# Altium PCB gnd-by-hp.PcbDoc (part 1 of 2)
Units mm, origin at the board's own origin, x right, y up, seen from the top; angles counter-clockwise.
Board outline 80 x 100 mm, 4 copper layers (Top Layer, Mid-Layer 1, Internal Plane 1, Bottom Layer); 158 components, 114 nets, 565 pads, 335 vias.
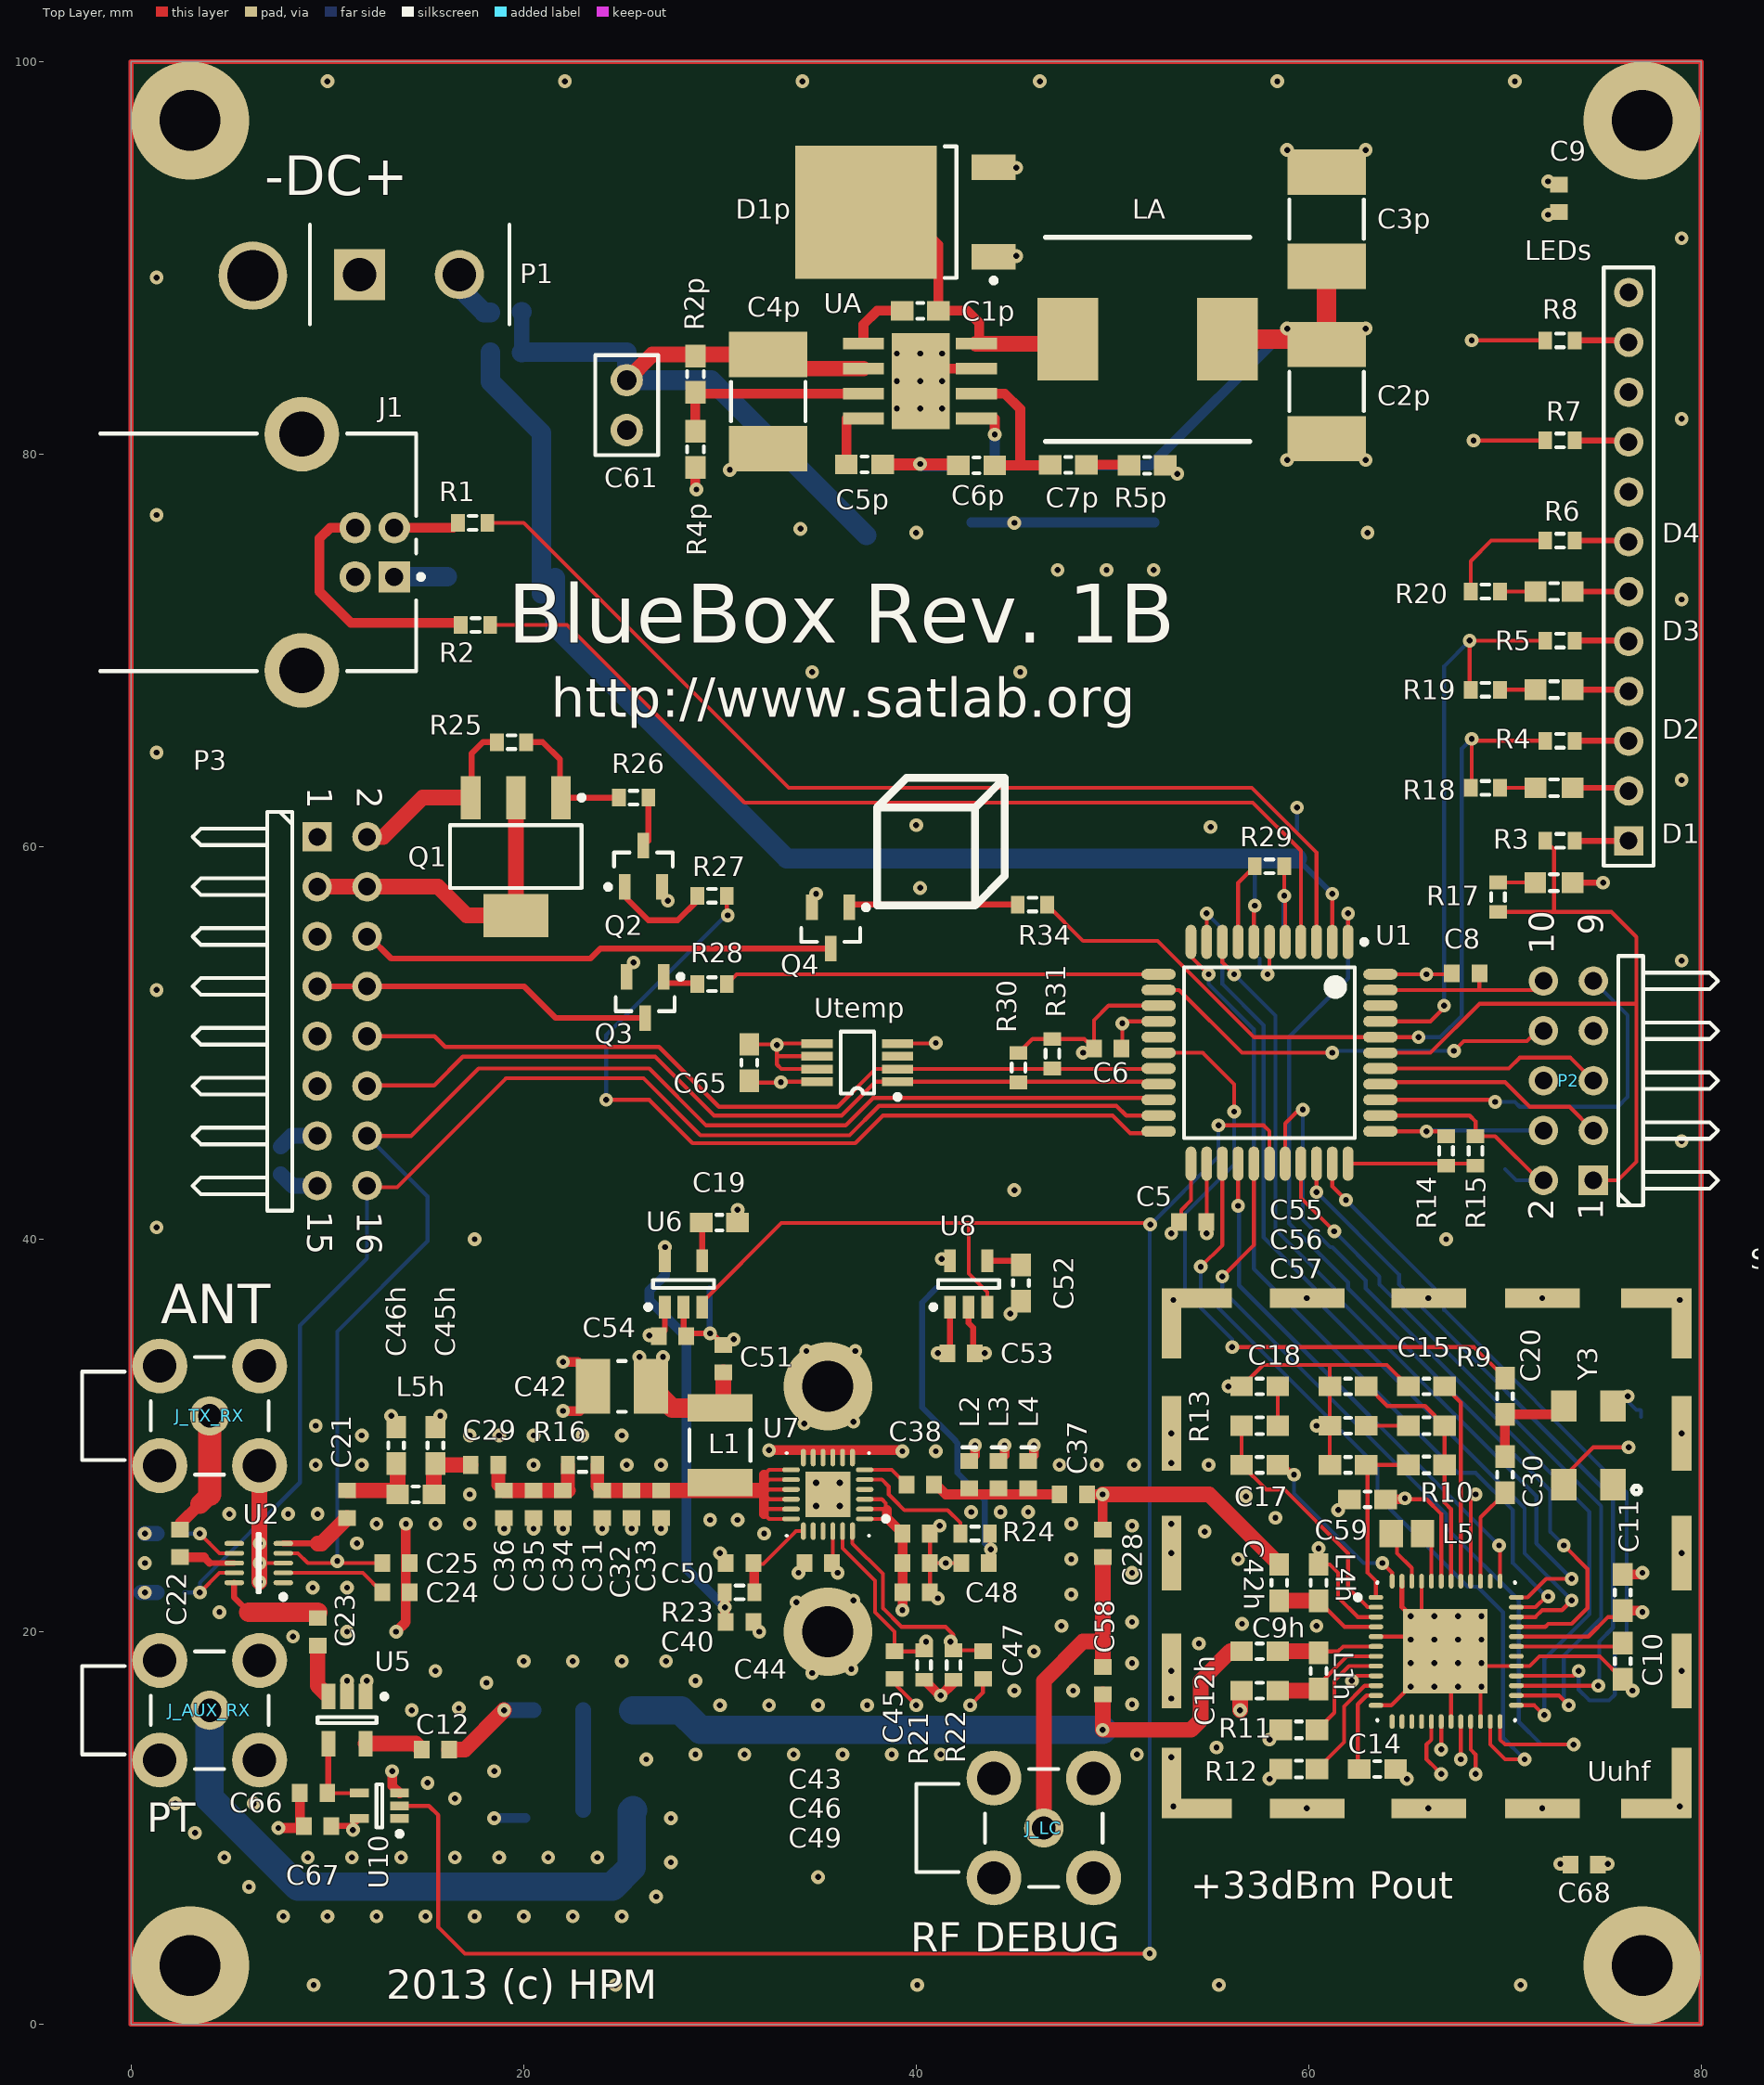
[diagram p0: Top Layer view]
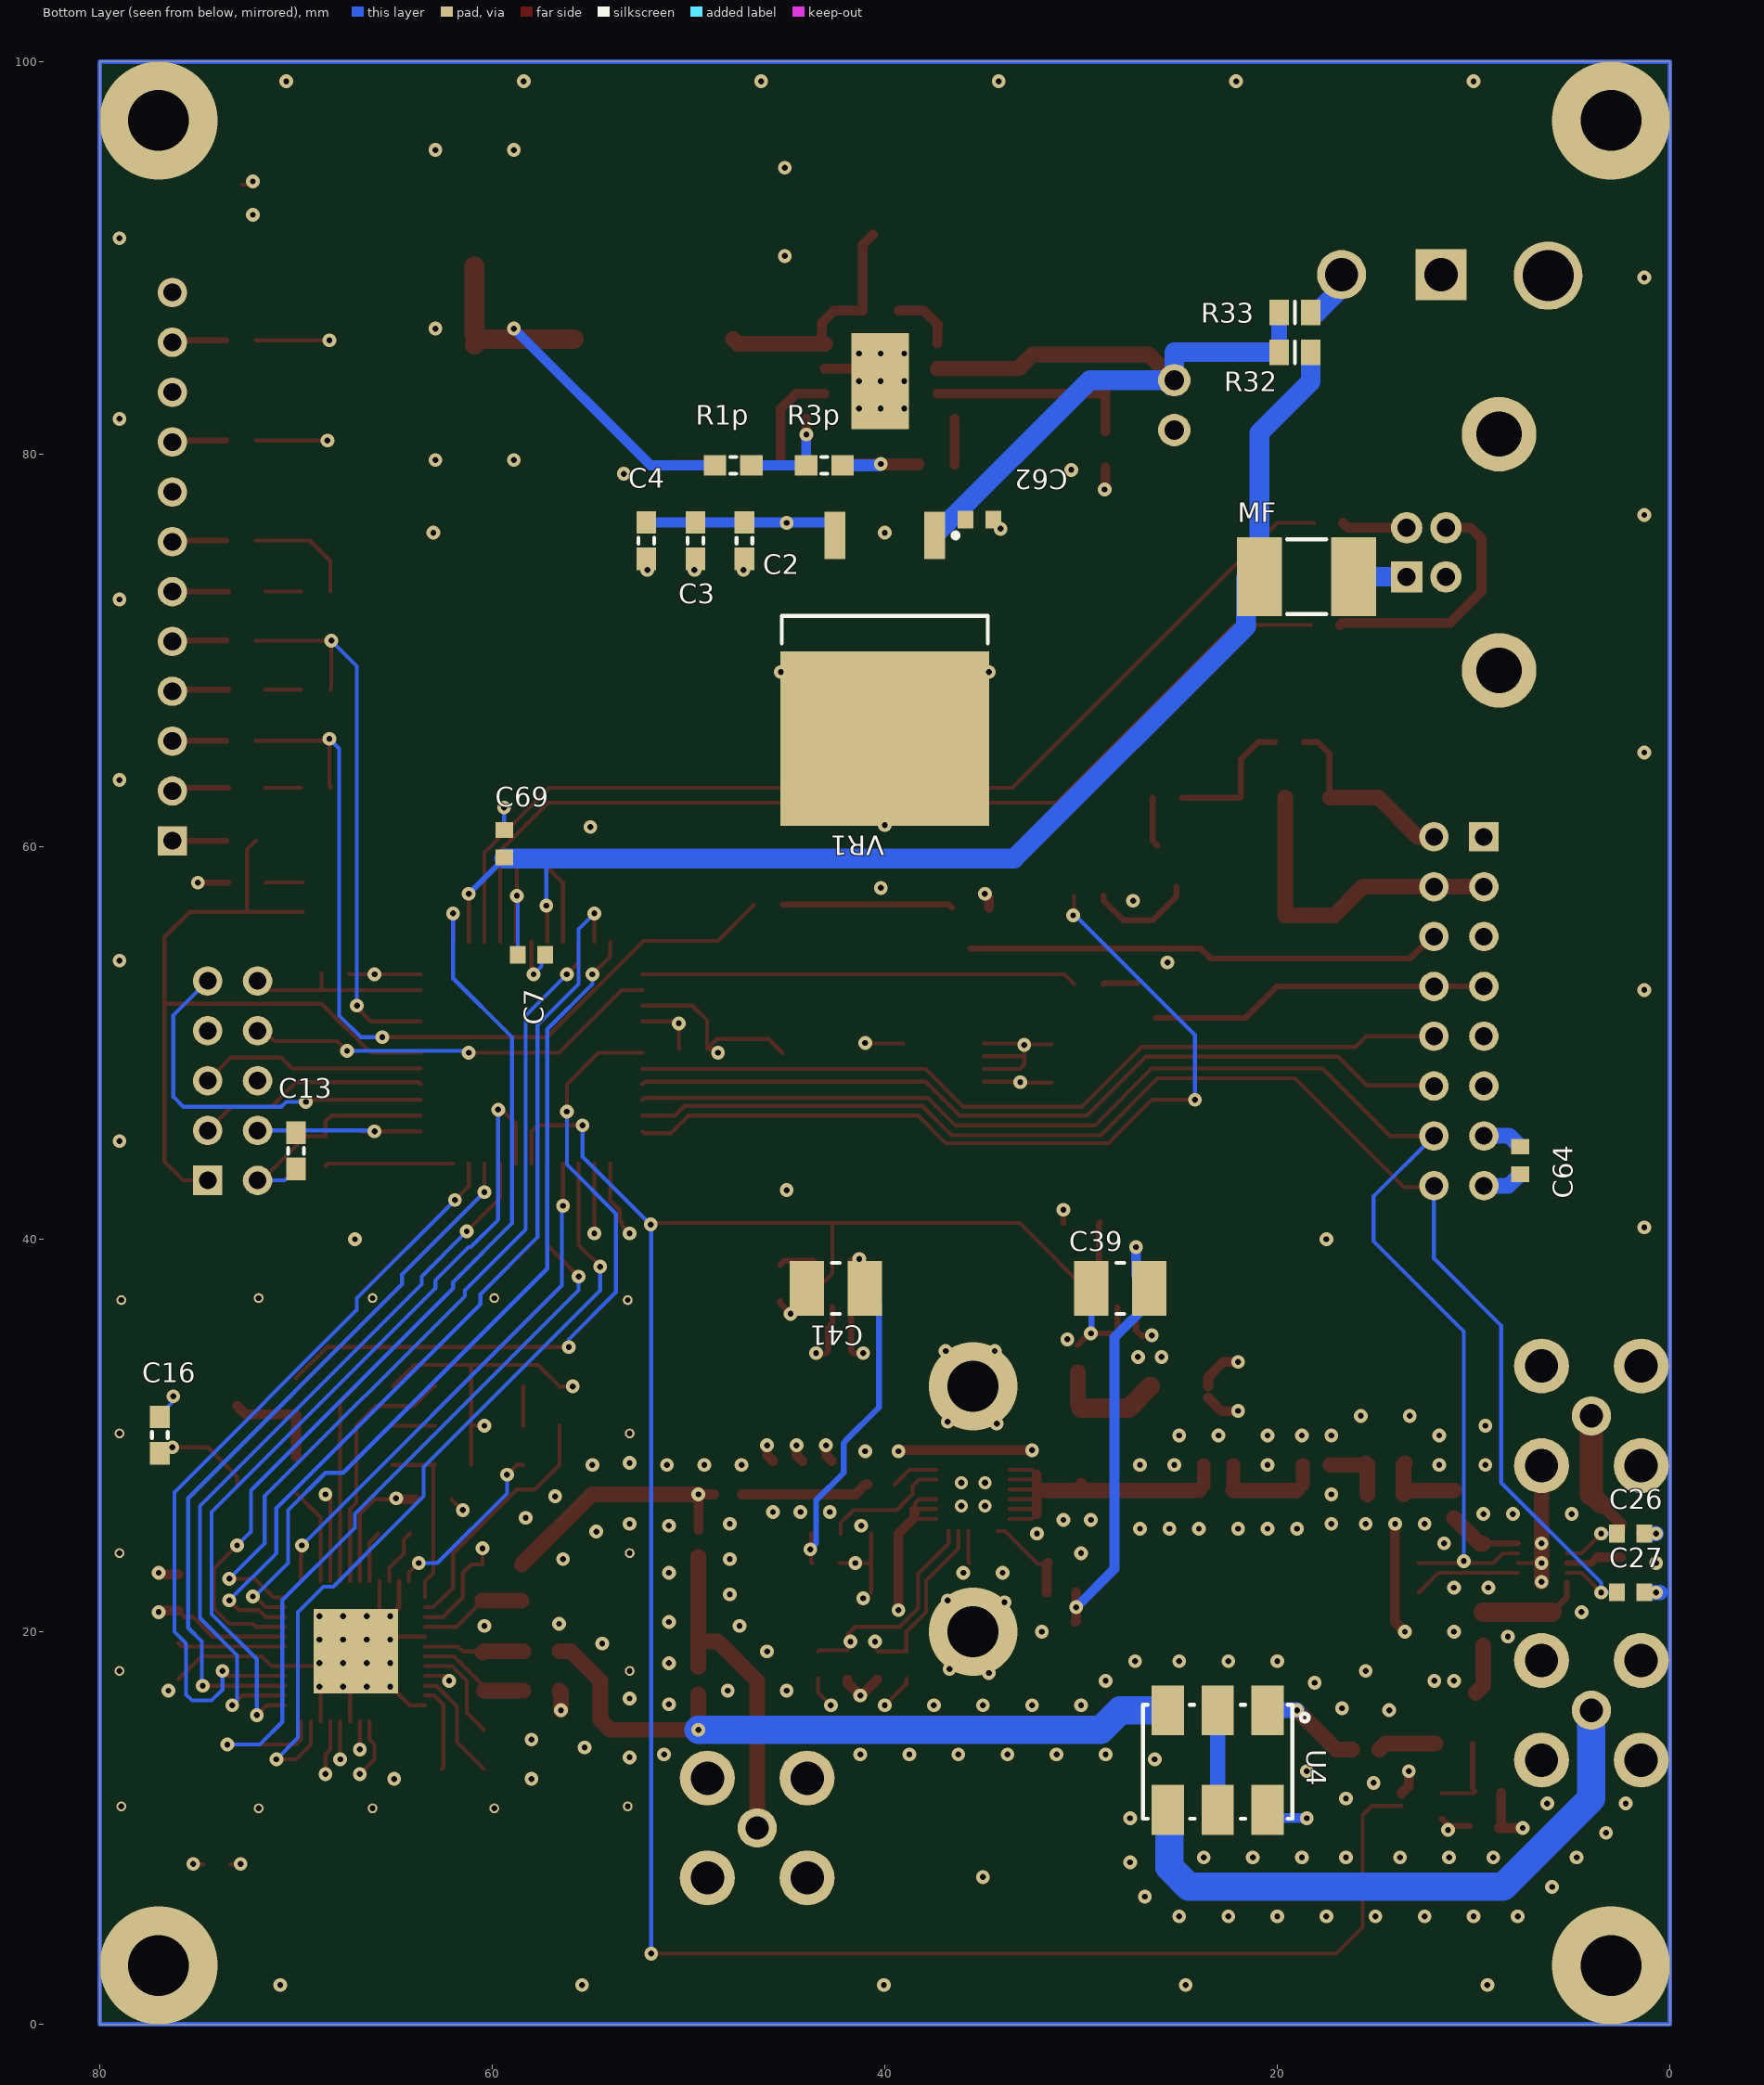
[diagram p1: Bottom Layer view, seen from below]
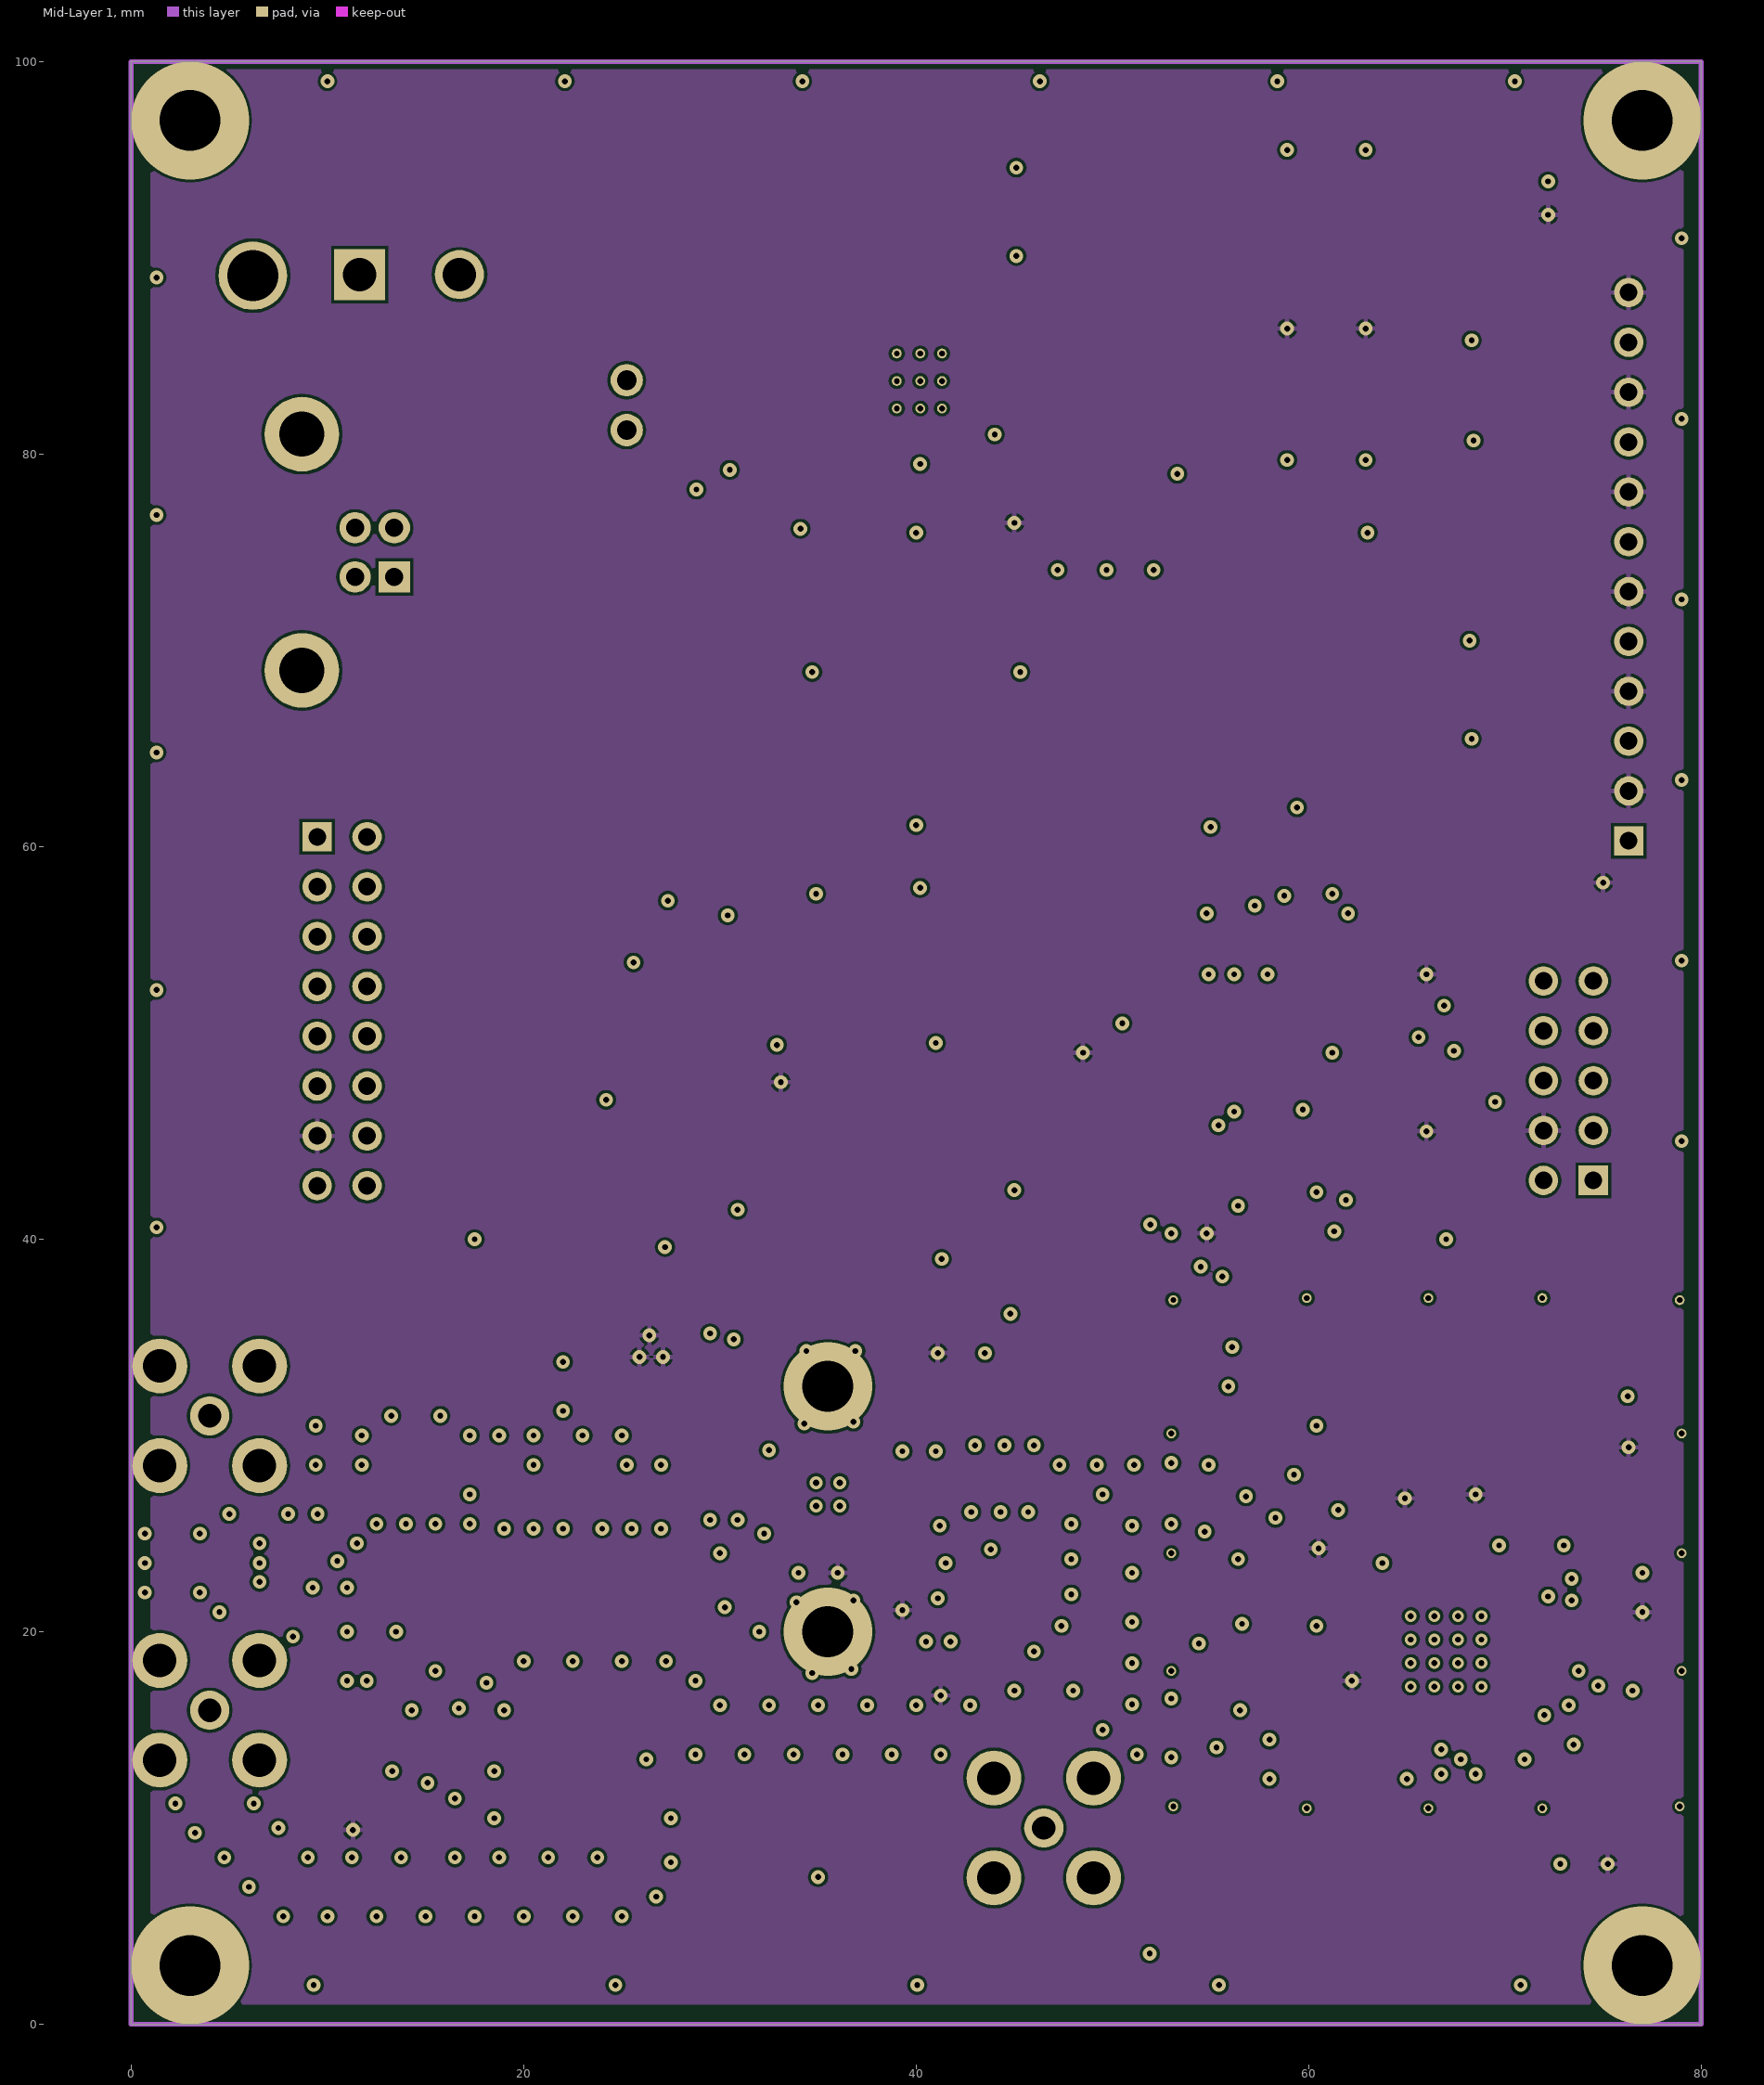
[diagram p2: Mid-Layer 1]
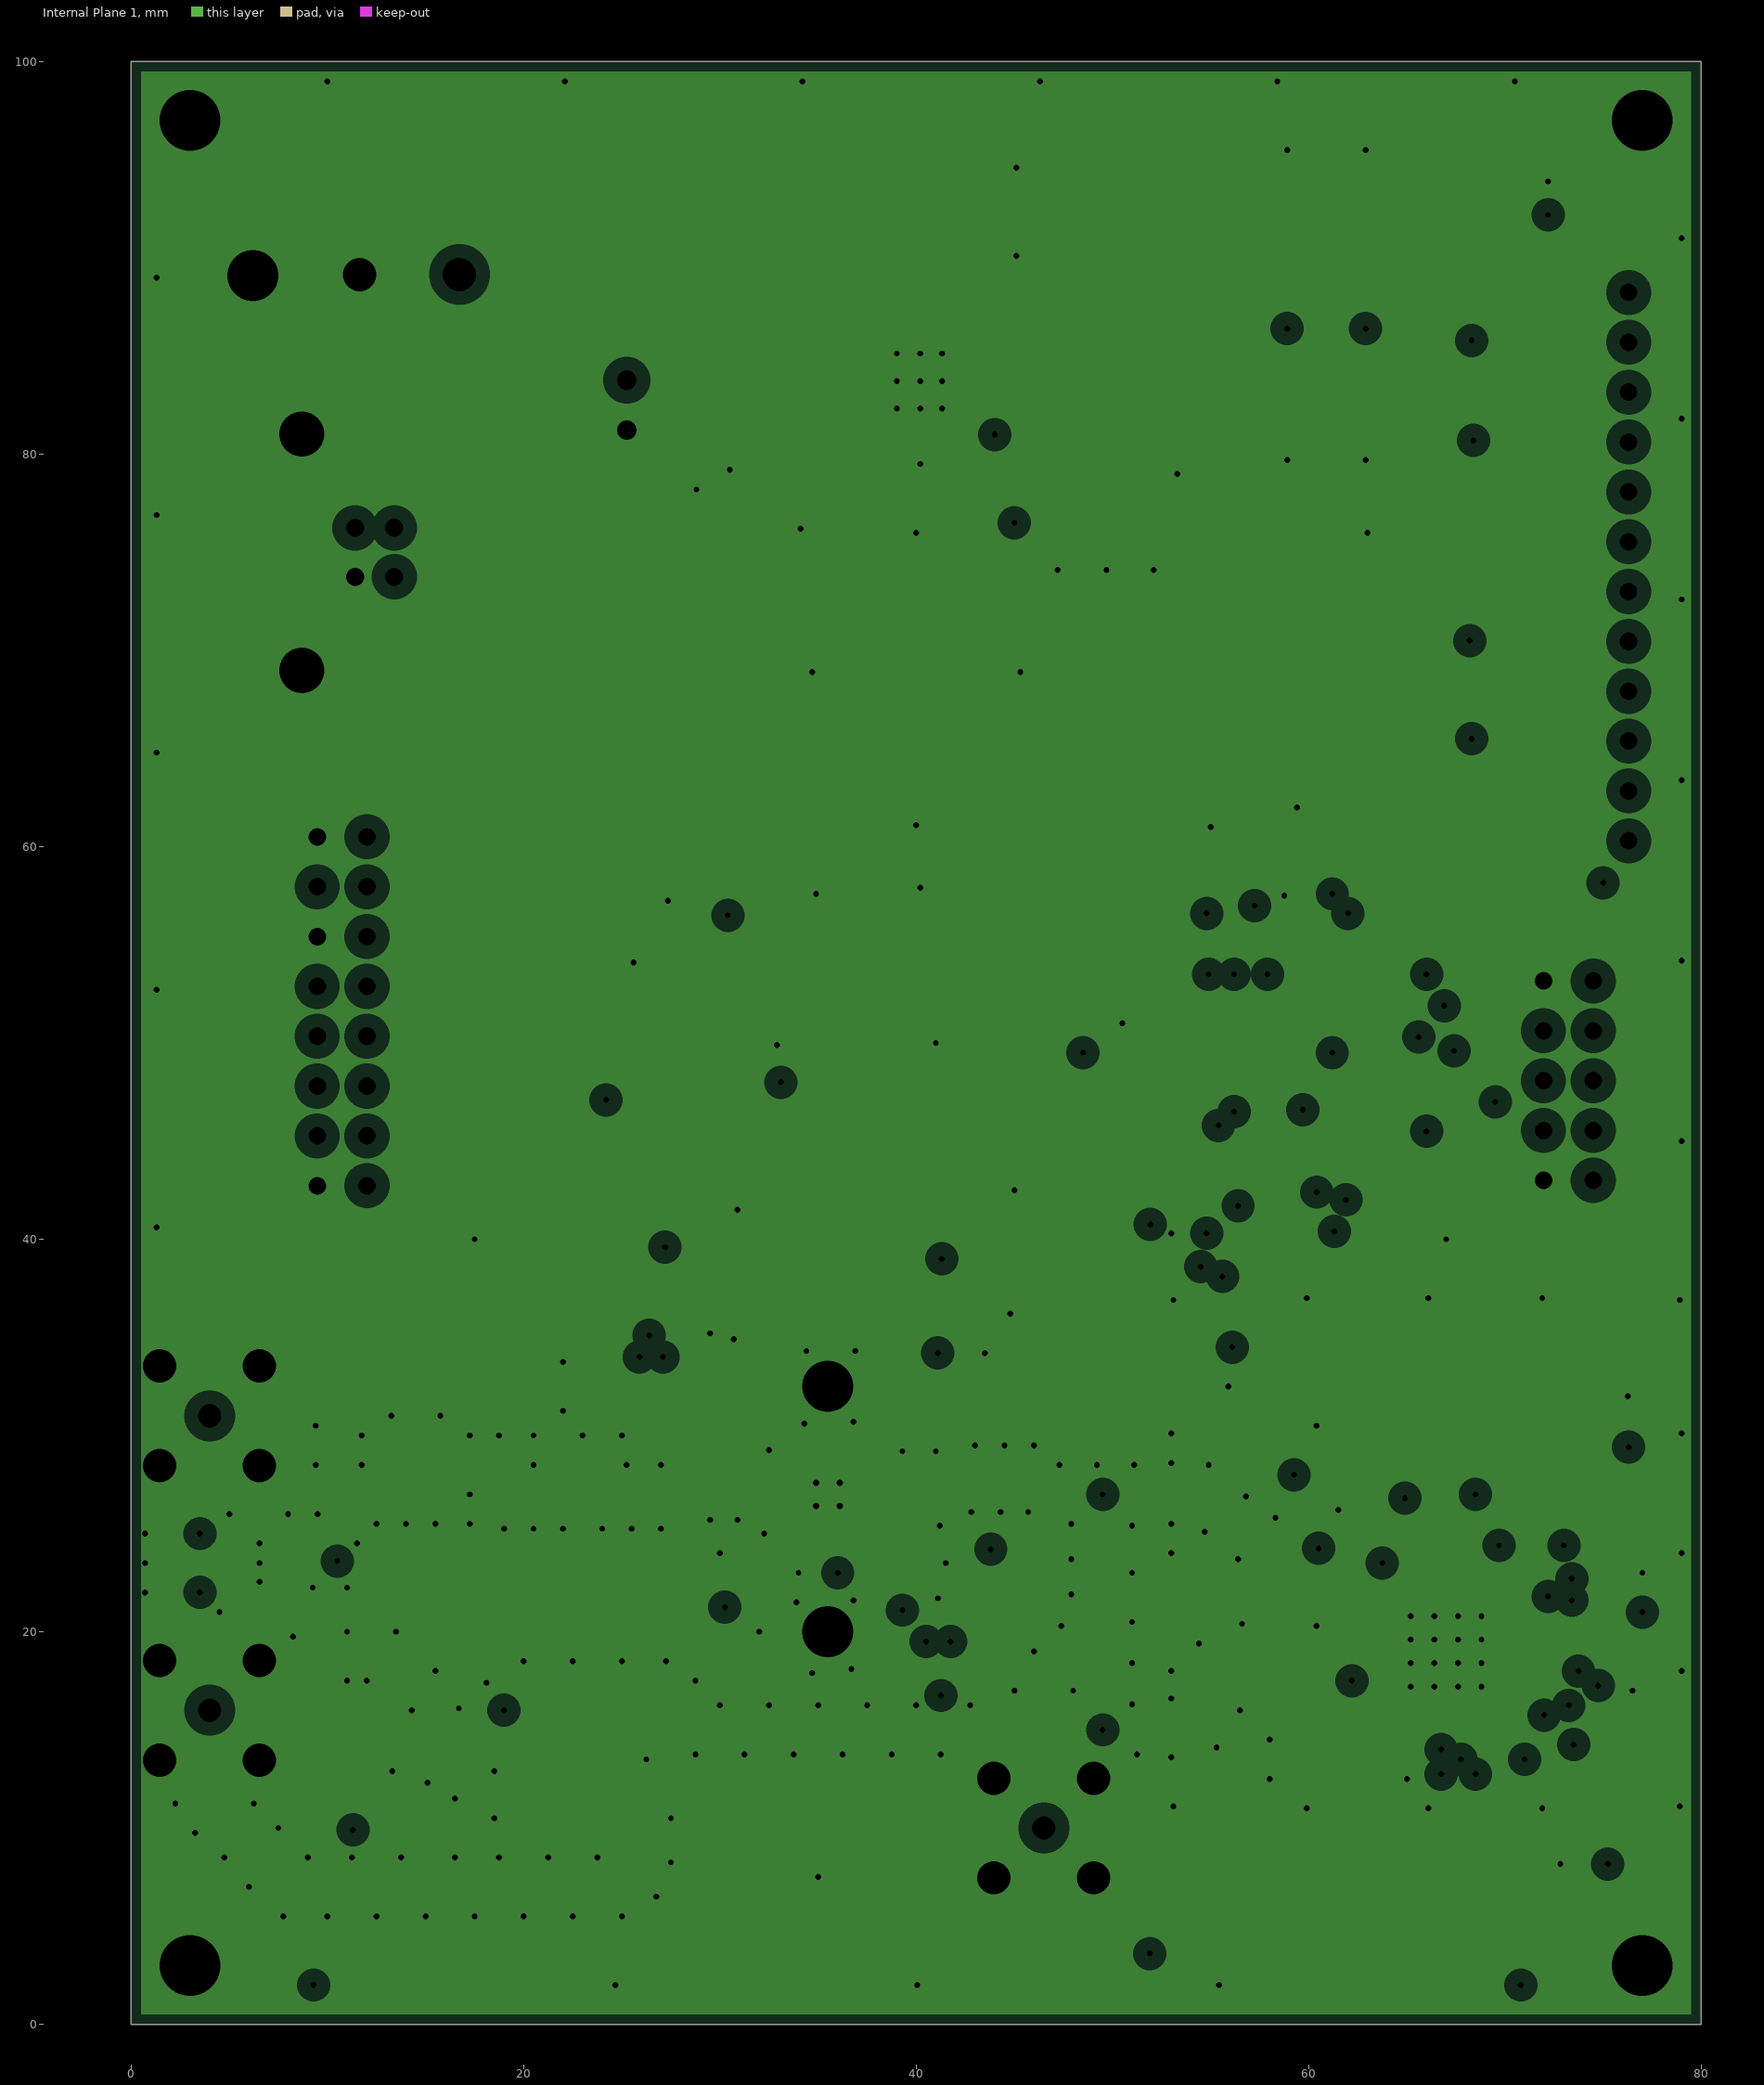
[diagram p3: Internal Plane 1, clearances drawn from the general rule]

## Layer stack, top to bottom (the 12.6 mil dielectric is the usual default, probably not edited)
Top Layer: signal copper 0.0356
Dielectric: core 0.32, FR-4, Dk 4.8
Mid-Layer 1: signal copper 0.0356
Dielectric: prepreg 0.32, FR-4, Dk 4.8
Internal Plane 1: plane copper 0.0356, net GND
Dielectric: core 0.32, FR-4, Dk 4.8
Bottom Layer: signal copper 0.0356

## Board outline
0,0 80,0 80,100 0,100

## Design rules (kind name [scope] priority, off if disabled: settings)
Clearance Clearance_1 [InNamedPolygon('a-gnd') Or  InNamedPolygon('a-gnd')] p1: gap=0.22
Clearance [All] p2: gap=0.15
HoleSize [All] p1: absolutevalues=TRUE maxlimit=4 minlimit=0.3 maxpercent=80.000 minpercent=20.000
HoleToHoleClearance [All] p1: gap=0.1 allowstackedmicrovias=TRUE
MinimumSolderMaskSliver [All] p1: minsoldermaskwidth=0.1
PlaneClearance [All] p1: clearance=0.7
PlaneConnect [All] p1: planeconnectstyle=Direct reliefexpansion=0.3 reliefentries=4 reliefconductorwidth=0.3 reliefairgap=0.2
PolygonConnect PolygonConnect_1 [(InNet('GND') AND IsTrack) OR (InNet('GND') AND IsVia) OR (InNet('GND') AND Uuhf) vs IsNamedPolygon('a-gnd') Or  IsNamedPolygon('a-gnd')] p1: connectstyle=Direct reliefconductorwidth=0.254 reliefentries=4 polygonreliefangle="90 Angle"
PolygonConnect [All] p2: connectstyle=Relief reliefconductorwidth=0.254 reliefentries=4 polygonreliefangle="90 Angle"
RoutingVias [All] p1: holewidth=0.3 width=0.7 viastyle="Through Hole" minholewidth=0.3 minwidth=0.7 maxholewidth=2 maxwidth=1.27
SilkToSilkClearance [All] p1: silktosilkclearance=0.1
SilkscreenOverComponentPads [All] p1: minsilkscreentomaskgap=0.1
SolderMaskExpansion [All] p1: expansion=0.102
Width [All] p1: maxlimit=4 minlimit=0.2 preferedwidth=0.2
21 further rules are at their usual default settings.

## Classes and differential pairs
net class pa_Nets: GND Net*_4 Net*_7 Net*_8 Net*_9 Net*_10 Net*_11 Net*_12 Net*_20 Net*_21 NetC19_2 NetC29_1 NetC37_1 NetC38_1 NetC45_1 NetC47_2 NetC50_2 NetC52_2 NetR24_1 NetU6_3 NetU6_4 NetU8_3 PA_BIAS_EN PA_IN PA_OUT RFOUT VCC VREG1 VREG2
component class gnd-by-hp: C1 C2 C5 C6 C7 C8 C9 C60 C61 C62 C63 C64 C65 C67 C68 C69 C? D1 D2 D3 D4 H1 H2 H3 H4 H5 H6 J1 J2 J4 LEDs MF P1 P2 P3 Q1 Q2 Q3 Q4 R1 R2 R3 R4 R5 R6 R7 R8 R14 R15 R17 R18 R19 R20 R25 R26 R27 R28 R29 R30 R31 R32 R33 R34 U1 U10 Utemp VR1 Y1
component class radio: C3 C4 C9h C10 C11 C12 C12h C13 C14 C15 C16 C17 C18 C20 C21 C22 C23 C24 C25 C26 C27 C28 C30 C42h C45h C46h C55 C56 C57 C58 C59 C66 J_AUX_RX J_LC J_P J_TX_RX L1h L4h L5 L5h R9 R10 R11 R12 R13 S1 S2 SMA1 U2 U3 U4 U5 Uuhf Y3
component class pa: C19 C29 C31 C32 C33 C34 C35 C36 C37 C38 C39 C40 C41 C42 C43 C44 C45 C46 C47 C48 C49 C50 C51 C52 C53 C54 J_D1 L1 L2 L3 L4 R16 R21 R22 R23 R24 U6 U7 U8
net class gnd-by-hp_Nets: 12V CE CLK_OUT D+ D- DATA_CLK DATA_IO EXT_BEKO_PTT EXT_BEKO_PTT_C EXT_LNA_CONTROL EXT_LNA_CONTROL_C GND LED_P LED_R LED_T LED_U1 LED_U2 LED_U3 LNA_V MUXOUT NetC7_1 NetD1_2 NetD2_2 NetD3_2 NetD4_2 NetJ1_1 NetLEDs_1 NetLEDs_3 NetLEDs_5 NetLEDs_7 NetLEDs_9 NetLEDs_11 NetP2_6 NetP2_7 NetP3_9 NetP3_10 NetP3_11 NetP3_12 NetP3_13 NetP3_15 NetP3_17 NetP3_19 NetQ1_1 NetQ2_1 NetQ2_3 NetQ3_1 NetQ4_1 NetR1_2 NetR2_2 NetR29_2 NetU1_9 NetU1_10 NetU1_11 NetU1_12 NetU1_16 NetU1_22 NetU1_26 NetU1_28 NetU1_40 NetU1_41 NetU1_42 NetUSB_4 NetUtemp_3 NetUtemp_5 NetUtemp_6 NetUtemp_7 PA_BIAS_EN PE2 PTT_TX_STAGE_1 RESET RF_RX_C RF_TX_C SCCLK SCL SDA SDATA SLE SREAD SWD TDI_MOSI TEST_A TMS_RST V_BUS VCC VCC_AUX VCC_POWER_DC X1
net class radio_Nets: CE CLK_OUT CPOUT CREG3 DATA_CLK DATA_IO GND L1 L2 LNA_V MUXOUT MUXOUT2 NetC9h_2 NetC10_2 NetC12_2 NetC12h_2 NetC14_2 NetC17_1 NetC17_2 NetC18_1 NetC20_1 NetC21_1 NetC21_2 NetC22_1 NetC23_1 NetC24_1 NetC26_1 NetC28_1 NetC28_2 NetC30_2 NetC42h_1 NetC56_2 NetR11_1 NetR12_2 NetU2_1 NetU3_1 NetU3_2 NetU3_3 NetU3_4 NetU3_5 NetU4_2 NetU5_4 NetU10_1 NetUuhf_13 NetUuhf_14 NetUuhf_15 NetUuhf_16 NetUuhf_17 NetUuhf_18 NetUuhf_20 NetUuhf_21 NetUuhf_30 NetUuhf_38 NetY3_1 PA_IN PA_OUT RF_LC RF_RX RF_RX_AUX RF_RX_C RF_RX_LNA RF_RX_MOD RF_RX_TX RF_TX_C SCCLK SDATA SLE SREAD SWD TEST_A VCC VCOIN X1
net class Supply: PHA VCC
component class power: C1p C2p C3p C4p C5p C6p C7p D1p LA R1p R2p R3p R4p R5p UA

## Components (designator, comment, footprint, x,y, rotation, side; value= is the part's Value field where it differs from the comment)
C1p "Capacitor" C06 40.206,87.306 r0 top
C2 "Capacitor" C06 47.15,75.6 r90 bottom
C2p "CapacitorBig" Cap1812-large 60.907,83.192 r90 top
C3 "Cap Semi" C06 49.65,75.6 r90 bottom
C3p "CapacitorBig" Cap1812-large 60.909,91.973 r270 top
C4 "Cap Semi" C06 52.15,75.6 r90 bottom
C4p "CapacitorBig" Cap1812-large 32.459,82.684 r90 top
C5 "Cap Semi" CAPC1608L 54.077,40.869 r0 top
C5p "Capacitor" C06 37.363,79.477 r180 top
C6 "Cap Semi" CAPC1608L 49.759,49.708 r180 top
C6p "Capacitor" C06 43.076,79.432 r180 top
C7 "Cap Semi" CAPC1608L 58,54.5 r0 bottom
C7p "Capacitor" C06 47.75,79.458 r0 top
C8 "Cap Semi" CAPC1608L 67.996,53.543 r0 top
C9 "Cap Semi" CAPC1608L 72.746,93.04 r270 top
C9h "Cap Semi" C06 57.5,19 r0 top
C10 "Cap Semi" C06 76,18.5 r90 top
C11 "Cap Semi" C06 76,22 r270 top
C12 "Cap Semi" CAPC1608L 15.5,14 r180 top
C12h "Cap Semi" C06 57.5,17 r0 top
C13 "Cap Semi" C06 70,44.5 r90 bottom
C14 "Cap Semi" C06 63.5,13 r180 top
C15 "Cap Semi" C06 66,32.5 r0 top
C16 "Cap Semi" C06 76.937,30.023 r270 bottom
C17 "Cap Semi" C06 57.5,28.5 r0 top
C18 "Cap Semi" C06 57.5,32.5 r180 top
C19 "Capacitor" C06 29.972,40.843 r180 top
C20 "Cap Semi" C06 70,32 r90 top
C21 "Cap Semi" CAPC1608L 11,26.5 r270 top
C22 "Cap Semi" CAPC1608L 2.5,24.5 r90 top
C23 "Cap Semi" CAPC1608L 9.5,20 r90 top
C24 "Cap Semi" CAPC1608L 13.5,22 r0 top
C25 "Cap Semi" CAPC1608L 13.5,23.5 r0 top
C26 "Cap Semi" CAPC1608L 2,25 r180 bottom
C27 "Cap Semi" CAPC1608L 2,22 r180 bottom
C28 "Cap Semi" CAPC1608L 49.5,24.5 r270 top
C29 "Cap Semi" CAPC1608L 18,28.5 r180 top
C30 "Cap Semi" C06 70,28 r270 top
C31 "Cap Semi" CAPC1608L 24,26.5 r90 top
C32 "Cap Semi" CAPC1608L 25.5,26.5 r90 top
C33 "Cap Semi" CAPC1608L 27,26.5 r90 top
C34 "Cap Semi" CAPC1608L 22,26.5 r90 top
C35 "Cap Semi" CAPC1608L 20.5,26.5 r90 top
C36 "Cap Semi" CAPC1608L 19,26.5 r90 top
C37 "Cap Semi" CAPC1608L 48,27 r0 top
C38 "Cap Semi" CAPC1608L 40.2,27.5 r0 top
C39 "CapacitorBig" C1210 28,37.5 r0 bottom
C40 "Cap Semi" CAPC1608L 31,20.5 r180 top
C41 "CapacitorBig" C1210 42.5,37.5 r180 bottom
C42 "CapacitorBig" C1210 25,32.5 r180 top
C42h "Cap Semi" C06 58.5,22.5 r90 top
C43 "Cap Semi" CAPC1608L 40,25 r0 top
C44 "Cap Semi" CAPC1608L 35,23.5 r180 top
C45 "Cap Semi" CAPC1608L 38.9,18.3 r270 top
C45h "Cap Semi" C06 15.5,29.5 r270 top
C46 "Cap Semi" CAPC1608L 40,23.5 r0 top
C46h "Cap Semi" C06 13.5,29.5 r270 top
C47 "Cap Semi" CAPC1608L 43.4,18.3 r90 top
C48 "Cap Semi" CAPC1608L 43,23.5 r180 top
C49 "Cap Semi" CAPC1608L 40,22 r0 top
C50 "Cap Semi" CAPC1608L 31,23.5 r0 top
C51 "Cap Semi" CAPC1608L 30.175,33.909 r270 top
C52 "Capacitor" C06 45.339,37.77 r90 top
C53 "Cap Semi" CAPC1608L 42.291,34.188 r180 top
C54 "Cap Semi" CAPC1608L 27.584,35.052 r180 top
C55 "Cap Semi" C06 62,32.5 r0 top
C56 "Cap Semi" C06 62,30.5 r0 top
C57 "Cap Semi" C06 62,28.5 r0 top
C58 "Cap Semi" CAPC1608L 49.5,17.5 r90 top
C59 "Cap Semi" C06 63,26.746 r0 top
C61 "Cap" CAPR2.54-5.1x3.2 25.25,82.5 r90 top
C62 "Cap Semi" CAPC1608L 35.179,76.657 r0 bottom
C64 "Cap Semi" CAPC1608L 7.626,44.018 r90 bottom
C65 "Capacitor" C06 31.5,49 r270 top
C66 "Cap Semi" CAPC1608L 9.296,11.786 r180 top
C67 "Cap Semi" CAPC1608L 9.505,10.1 r0 top
C68 "Cap Semi" CAPC1608L 74.041,8.141 r0 top
C69 "Cap Semi" CAPC1608L 59.394,60.147 r270 bottom
D1 "LED" L06 72.492,58.166 r180 top
D1p "MBRD360" TO228P1003X238-3N 39.446,92.329 r180 top
D2 "LED" L06 72.5,63 r180 top
D3 "LED" L06 72.5,68 r180 top
D4 "LED" L06 72.5,73 r180 top
J1 "1-1470156-1" 1-1470156 -1.6,75 r180 top
J_AUX_RX "COAX-F" MCX5.08-H5 4,16 r0 top
J_LC "COAX-F" MCX5.08-H5 46.5,10 r0 top
J_TX_RX "COAX-F" MCX5.08-H5 4,31 r0 top
L1 "Inductor" INDC4532L 30,29.5 r90 top
L1h "Inductor" C06 60.5,18 r90 top
L2 "Inductor" INDC1608L 42.7,28 r270 top
L3 "Inductor" INDC1608L 44.2,28 r270 top
L4 "Inductor" INDC1608L 45.7,28 r270 top
L4h "Inductor" C06 60.5,22.5 r90 top
L5 "Inductor" INDC2012L 65,25 r0 top
L5h "Inductor" C06 14.5,27 r180 top
LA "Inductor" B82464-G4 46.455,91.193 r0 top
LEDs "Header 12" HDR1X12 76.3,60.3 r90 top
MF "Multifuse" Cap1812-large 18.511,73.76 r180 bottom
P1 "Header 2" HDR1X2 19.954,88.163 r0 top
P2 "Header 5X2H" HDR2X5H 74.5,43 r90 top
P3 "Header 8X2H" HDR2X8H 9.48,60.503 r270 top
Q1 "BSP250" SOT223_N 19.6,59.5 r270 top
Q2 "BSH105" SOT23_N 26.1,59 r90 top
Q3 "BSH105" SOT23_N 26.191,52.324 r270 top
Q4 "BSH105" SOT23_N 35.64,55.855 r270 top
R1 "Res Semi" RESC1608L 17.4,76.5 r0 top
R1p "Resistor" R06 47.725,79.432 r0 bottom
R2 "Res Semi" RESC1608L 17.546,71.296 r0 top
R2p "Res Semi" R06 28.751,84.081 r90 top
R3 "Res Semi" RESC1608L 72.8,60.3 r0 top
R3p "Resistor" R06 43.076,79.432 r0 bottom
R4 "Res Semi" RESC1608L 72.8,65.4 r0 top
R4p "Res Semi" R06 28.751,80.245 r90 top
R5 "Res Semi" RESC1608L 72.8,70.5 r0 top
R5p "Resistor" R06 51.763,79.432 r0 top
R6 "Res Semi" RESC1608L 72.8,75.6 r0 top
R7 "Res Semi" RESC1608L 72.8,80.7 r0 top
R8 "Res Semi" RESC1608L 72.8,85.8 r0 top
R9 "Res Semi" R06 66,30.5 r0 top
R10 "Res Semi" R06 66,28.5 r0 top
R11 "Res Semi" R06 59.5,15 r180 top
R12 "Res Semi" R06 59.5,13 r0 top
R13 "Res Semi" R06 57.5,30.5 r0 top
R14 "Res Semi" RESC1608L 67,44.5 r90 top
R15 "Res Semi" RESC1608L 68.5,44.5 r270 top
R16 "Res Semi" RESC1608L 23,28.5 r180 top
R17 "Res Semi" RESC1608L 69.647,57.429 r270 top
R18 "Res Semi" RESC1608L 69,63 r180 top
R19 "Res Semi" RESC1608L 69,68 r180 top
R20 "Res Semi" RESC1608L 69,73 r180 top
R21 "Res Semi" RESC1608L 40.4,18.3 r270 top
R22 "Res Semi" RESC1608L 41.9,18.3 r270 top
R23 "Res Semi" RESC1608L 31,22 r0 top
R24 "Res Semi" RESC1608L 43,25 r0 top
R25 "Res Semi" RESC1608L 19.38,65.329 r180 top
R26 "Res Semi" RESC1608L 25.6,62.5 r0 top
R27 "Res Semi" RESC1608L 29.6,57.5 r0 top
R28 "Res Semi" RESC1608L 29.6,53 r0 top
R29 "Res Semi" RESC1608L 58,59 r180 top
R30 "Res Semi" RESC1608L 45.212,48.743 r90 top
R31 "Res Semi" RESC1608L 46.939,49.454 r90 top
R32 "Res Semi" RESC2012L 19.101,85.192 r0 bottom
R33 "Res Semi" RESC2012L 19.101,87.224 r0 bottom
R34 "Res Semi" RESC1608L 45.923,57.048 r0 top
S2 "rf_shield" rf_can_shield 52.5,37.5 r270 top locked
U1 "ATmega32u4" 44A_N 58,49.5 r270 top
U2 "RX/TX Switch" FLP10 6.5,23.5 r180 top
U4 "ADP-2-1" ADP-2-1 20.5,16 r270 bottom
U5 "RF2314" SOT95P280X144-5M 11,15.5 r270 top
U6 "TC1185" "SOT23 - 5 for microchip" 28.143,37.719 r90 top
U7 "RF6886TR7" QFN24-4-4 35.5,27 r180 top
U8 "TC1185" "SOT23 - 5 for microchip" 42.672,37.719 r90 top
U10 "MC74HC inv" "SOT353 for MC74HC" 12.649,11.125 r180 top
UA "TPS54332DDA" 8SO_PowerPAD 37.311,85.63 r0 top
Utemp "DS75LXU+" uSOP8 37,49 r90 top
Uuhf "ADF7021" QFN50P700X700X100-48M 67,19 r0 top
VR1 "Volt Reg" TO254P1510-3_4N 40.005,69.063 r270 bottom
Y3 "FOX924B" Fox924 73,27.5 r90 top

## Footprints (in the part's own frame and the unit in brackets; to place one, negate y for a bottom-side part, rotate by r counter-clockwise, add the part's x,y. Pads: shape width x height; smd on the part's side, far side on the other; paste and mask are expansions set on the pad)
1-1470156 [mm] "Connector; USB1.1, Type B, Thru-Hole; 4 Position; Right Angle"
  rect 1.6x1.6 hole 0.92: 1(-15.01,1.25)
  round 1.6 hole 0.92: 2(-15.01,-1.25) 3(-13.01,-1.25) 4(-13.01,1.25)
  round 3.8 hole 2.3: 5(-10.3,6.02) 6(-10.3,-6.02)
  silkscreen extent -16.49,-6.05 -0.02,6.05
8SO_PowerPAD [mm] "TPS SO8 PowerPAD (for TPS54332)"
  rect 2.1x0.6 smd: 1(0,0) 2(0,-1.27) 3(0,-2.54) 4(0,-3.81) 5(5.75,-3.81) 6(5.75,-2.54) 7(5.75,-1.27) 8(5.75,0)
  round 0.5 hole 0.3: 9(1.7,-3.3) 9(1.7,-1.9) 9(1.7,-0.5) 9(2.9,-3.3) 9(2.9,-1.9) 9(2.9,-0.5) 9(4,-3.3) 9(4,-1.9) 9(4,-0.5)
  rect 2.94x4.89 smd: 9(2.921,-1.905)
  rect 2.94x4.89 smd far side: 9(2.921,-1.905)
  body extent 0.85,-4.5 4.85,0.58, height 2.5
44A_N [mm] "Thin QFP, 44-Leads, Body 10x10mm, Pitch 0.8mm, IPC Medium Density"
  oval 1.75x0.55 smd: 1(-5.65,4) 2(-5.65,3.2) 3(-5.65,2.4) 4(-5.65,1.6) 5(-5.65,0.8) 6(-5.65,0) 7(-5.65,-0.8) 8(-5.65,-1.6) 9(-5.65,-2.4) 10(-5.65,-3.2) 11(-5.65,-4) 23(5.65,-4) 24(5.65,-3.2) 25(5.65,-2.4) 26(5.65,-1.6) 27(5.65,-0.8) 28(5.65,0) 29(5.65,0.8) 30(5.65,1.6) 31(5.65,2.4) 32(5.65,3.2) 33(5.65,4)
  oval 0.55x1.75 smd: 12(-4,-5.65) 13(-3.2,-5.65) 14(-2.4,-5.65) 15(-1.6,-5.65) 16(-0.8,-5.65) 17(0,-5.65) 18(0.8,-5.65) 19(1.6,-5.65) 20(2.4,-5.65) 21(3.2,-5.65) 22(4,-5.65) 34(4,5.65) 35(3.2,5.65) 36(2.4,5.65) 37(1.6,5.65) 38(0.8,5.65) 39(0,5.65) 40(-0.8,5.65) 41(-1.6,5.65) 42(-2.4,5.65) 43(-3.2,5.65) 44(-4,5.65)
  silkscreen extent -5.77,-4.35 4.35,4.95, body extent -5,-5 5,5, height 1.2
ADP-2-1 [mm]
  rect 2.54x1.65 smd: 1(0,0) 2(0,-2.54) 3(0,-5.08) 4(5.08,-5.08) 5(5.08,-2.54) 6(5.08,0)
  silkscreen extent -0.28,-6.35 5.52,2.1
B82464-G4 [mm] "SMT Power Inductors B82464-G4"
  rect 3.1x4.2 smd: 1(1.27,-5.334) 2(9.398,-5.334)
  silkscreen extent 0.14,-10.54 10.54,-0.14, body extent 0.33,-10.35 10.33,-0.35, height 5
C06 [mm] "Chip Capacitor, 2-Leads, Body 1.6x0.8mm, IPC Low Density"
  rect 1.15x1 smd: 1(-0.925,0) 2(0.925,0)
  silkscreen extent -0.15,-0.4 0.15,0.4, body extent -0.8,-0.41 0.8,0.41, height 0.82
C1210 [mm] "Chip Capacitor, 2-Leads, Body 3.2x2.5mm, IPC Low Density"
  rect 1.75x2.8 smd: 1(-1.475,0) 2(1.475,0)
  silkscreen extent -0.2,-1.3 0.2,1.3, body extent -1.75,-1.35 1.75,1.35, height 2.7
Cap1812-large [mm] "Chip Resistor; Body 1812"
  rect 2.3x4 smd: 1(-2.4,0) 2(2.4,0)
  silkscreen extent -1,-1.9 1,1.9, body extent -2.89,-2 2.9,2, height 2.7
CAPC1608L [mm] "Chip Capacitor, Body 1.6x0.8mm, IPC High Density"
  rect 0.8x0.9 smd: 1(-0.7,0) 2(0.7,0)
  body extent -0.87,-0.48 0.87,0.48, height 1.3
CAPR2.54-5.1x3.2 [mm] "Capacitor, Ceramic, Thru-Hole, Dipped Radial; Body 5.1 x 3.2 mm (WxT) Pin Spacing 2.54 mm (typ)"
  round 1.65 hole 1: 1(-1.27,0) 2(1.27,0)
  silkscreen extent -2.55,-1.6 2.55,1.6
FLP10 [mm] "Used in NJG1519KC1-TE3, a IC MMIC Switch SP4t FLP10"
  oval 1x0.25 smd: 1(-1.25,1) 2(-1.25,0.5) 3(-1.25,0) 4(-1.25,-0.5) 5(-1.25,-1) 6(1.25,-1) 7(1.25,-0.5) 8(1.25,0) 9(1.25,0.5) 10(1.25,1)
  silkscreen extent -1.38,-1.5 0.08,1.85, body extent -1.2,-1.5 1.2,1.5, height 0.8
Fox924 [mm]
  rect 1.6x1.3 smd: 1(0,-2.5) 2(4,-2.5) 3(4,0) 4(0,0)
  silkscreen extent -0.47,-3.9 -0.08,-3.5, body extent -0.53,-2.83 4.5,0.35, height 1.5
HDR1X2 [mm] "Connector; Header; 2 Position"
  rect 2.6x2.6 hole 1.7: 1(-8.306,0.991)
  round 2.5 hole 1.7: 2(-3.226,0.991)
  silkscreen extent -10.85,-1.55 -0.69,3.53
HDR1X12 [mm] "Connector; Header; 12 Position"
  rect 1.5x1.5 hole 0.9: 1(0,0)
  round 1.5 hole 0.9: 2(2.54,0) 3(5.08,0) 4(7.62,0) 5(10.16,0) 6(12.7,0) 7(15.24,0) 8(17.78,0) 9(20.32,0) 10(22.86,0) 11(25.4,0) 12(27.94,0)
  silkscreen extent -1.27,-1.27 29.21,1.27
HDR2X5H [mm] "Connector; Header; 5x2 Position; Right Angle"
  rect 1.5x1.5 hole 0.9: 1(0,0)
  round 1.5 hole 0.9: 2(0,2.54) 3(2.54,0) 4(2.54,2.54) 5(5.08,0) 6(5.08,2.54) 7(7.62,0) 8(7.62,2.54) 9(10.16,0) 10(10.16,2.54)
  silkscreen extent -1.27,-6.35 11.43,-1.27
HDR2X8H [mm] "Connector; Header; 8x2 Position; Right Angle"
  rect 1.5x1.5 hole 0.9: 1(0,0)
  round 1.5 hole 0.9: 2(0,2.54) 3(2.54,0) 4(2.54,2.54) 5(5.08,0) 6(5.08,2.54) 7(7.62,0) 8(7.62,2.54) 9(10.16,0) 10(10.16,2.54) 11(12.7,0) 12(12.7,2.54) 13(15.24,0) 14(15.24,2.54) 15(17.78,0) 16(17.78,2.54)
  silkscreen extent -1.27,-6.35 19.05,-1.27
INDC1608L [mm] "Chip Inductor, Body 1.6x0.8mm, IPC High Density"
  rect 0.8x0.9 smd: 1(-0.7,0) 2(0.7,0)
  silkscreen extent -1.4,-0.35 -1.4,0.35, body extent -0.87,-0.48 0.87,0.48, height 0.55
INDC2012L [mm] "Chip Inductor, Body 2.0x1.2mm, IPC High Density"
  rect 1.2x1.4 smd: 1(-0.8,0) 2(0.8,0)
  body extent -1.1,-0.7 1.1,0.7, height 0.55
INDC4532L [mm] "Chip Inductor, Body 4.5x3.2mm, IPC High Density"
  rect 1.4x3.3 smd: 1(-1.9,0) 2(1.9,0)
  silkscreen extent -0.8,-1.55 0.8,1.55, body extent -2.4,-1.7 2.4,1.7, height 0.55
L06 [mm] "Chip LED, 2-Leads, Body 1.6x0.8mm, IPC Low Density"
  rect 1.1x1.05 smd: 1(-0.95,0) 2(0.95,0)
  silkscreen extent -0.2,-0.43 0.2,0.43, body extent -0.85,-0.45 0.85,0.45, height 0.9
MCX5.08-H5 [mm] "Connector; RF Coaxial, MCX, Thru-Hole; 5 Position; Right-Angle"
  round 2 hole 1.2: 1(0,0)
  round 2.8 hole 1.7: 2(-2.54,-2.54) 3(2.54,-2.54) 4(2.54,2.54) 5(-2.54,2.54)
  silkscreen extent -6.5,-3 3,3
QFN24-4-4 [mm] "QFN, 24-Leads, Body 4,2x4,2mm (max), Pitch 0,50mm, IPC Medium Density"
  oval 0.9x0.25 smd: 1(-1.875,1.25) 2(-1.875,0.75) 3(-1.875,0.25) 4(-1.875,-0.25) 5(-1.875,-0.75) 6(-1.875,-1.25) 13(1.875,-1.25) 14(1.875,-0.75) 15(1.875,-0.25) 16(1.875,0.25) 17(1.875,0.75) 18(1.875,1.25)
  oval 0.25x0.9 smd: 7(-1.25,-1.875) 8(-0.75,-1.875) 9(-0.25,-1.875) 10(0.25,-1.875) 11(0.75,-1.875) 12(1.25,-1.875) 19(1.25,1.875) 20(0.75,1.875) 21(0.25,1.875) 22(-0.25,1.875) 23(-0.75,1.875) 24(-1.25,1.875)
  rect 2.3x2.3 smd: 25(0,0)
  silkscreen extent -3.08,-2.1 2.1,2.1, body extent -2.07,-2.07 2.07,2.07, height 0.85
QFN50P700X700X100-48M [mm] "QFN, 48-Leads, Body 7,0x7,0mm (max), Pitch 0,50mm, IPC Low Density"
  oval 0.75x0.25 smd: 1(-3.575,2.75) 2(-3.575,2.25) 3(-3.575,1.75) 4(-3.575,1.25) 5(-3.575,0.75) 6(-3.575,0.25) 7(-3.575,-0.25) 8(-3.575,-0.75) 9(-3.575,-1.25) 10(-3.575,-1.75) 11(-3.575,-2.25) 12(-3.575,-2.75) 25(3.575,-2.75) 26(3.575,-2.25) 27(3.575,-1.75) 28(3.575,-1.25) 29(3.575,-0.75) 30(3.575,-0.25) 31(3.575,0.25) 32(3.575,0.75) 33(3.575,1.25) 34(3.575,1.75) 35(3.575,2.25) 36(3.575,2.75)
  oval 0.25x0.75 smd: 13(-2.75,-3.575) 14(-2.25,-3.575) 15(-1.75,-3.575) 16(-1.25,-3.575) 17(-0.75,-3.575) 18(-0.25,-3.575) 19(0.25,-3.575) 20(0.75,-3.575) 21(1.25,-3.575) 22(1.75,-3.575) 23(2.25,-3.575) 24(2.75,-3.575) 37(2.75,3.575) 38(2.25,3.575) 39(1.75,3.575) 40(1.25,3.575) 41(0.75,3.575) 42(0.25,3.575) 43(-0.25,3.575) 44(-0.75,3.575) 45(-1.25,3.575) 46(-1.75,3.575) 47(-2.25,3.575) 48(-2.75,3.575)
  rect 4.3x4.3 smd: 49(-0.05,0)
  rect 4.3x4.3 smd far side: 49(-0.05,0)
  silkscreen extent -4.62,-3.53 3.53,3.52, body extent -3.5,-3.5 3.5,3.5, height 1
R06 [mm] "Chip Resistor, 2-Leads, Body 1.6x0.8mm, IPC Low Density"
  rect 1.15x1.05 smd: 1(-0.925,0) 2(0.925,0)
  silkscreen extent -0.15,-0.43 0.15,0.43, body extent -0.8,-0.4 0.8,0.4, height 0.55
RESC1608L [mm] "Chip Resistor, Body 1.6x0.8mm, IPC High Density"
  rect 0.7x0.9 smd: 1(-0.75,0) 2(0.75,0)
  silkscreen extent -0.2,-0.35 0.2,0.35, body extent -0.85,-0.48 0.85,0.48, height 0.9
RESC2012L [mm] "Chip Resistor, Body 2.0x1.3mm, IPC High Density"
  rect 1x1.3 smd: 1(-0.8,0) 2(0.8,0)
  silkscreen extent 0,-0.55 0,0.55, body extent -1.07,-0.7 1.07,0.7, height 2.54
rf_can_shield [mm]
  rect 1x3.57 smd: 0(0.5,25.2) 0(0.5,1.8) 0(26.5,25.2) 0(26.5,1.8)
  rect 1x3.8 smd: 0(0.5,19.415) 0(0.5,13.615) 0(0.5,7.415) 0(26.5,19.415) 0(26.5,7.415) 0(26.5,13.615)
  round 0.5 hole 0.3: 0(0.5,19.4) 0(0.5,13.6) 0(0.5,7.4) 0(0.6,26.4) 0(0.6,0.6) 0(7.4,26.5) 0(7.4,0.5) 0(13.5,26.5) 0(13.5,0.5) 0(19.5,26.5) 0(19.5,0.5) 0(26.4,26.4) 0(26.4,0.6) 0(26.5,19.4) 0(26.5,7.4) 0(26.5,13.6)
  rect 3.57x1 smd: 0(1.8,26.5) 0(1.8,0.5) 0(25.2,26.5) 0(25.2,0.5)
  rect 3.8x1 smd: 0(7.4,26.5) 0(7.4,0.5) 0(13.5,26.5) 0(13.5,0.5) 0(19.5,26.5) 0(19.5,0.5)
  body extent 0.4,0.4 26.6,26.6, height 5.05
"SOT23 - 5 for microchip" [mm] "SOT23, 5-Leads, Body 3,1x3,2mm (max), Pitch 0,95mm, IPC Medium Density"
  rect 1.15x0.6 smd: 1(-1.175,0.95) 2(-1.175,0) 3(-1.175,-0.95) 4(1.175,-0.95) 5(1.175,0.95)
  silkscreen extent -1.3,-1.55 0.2,1.92, body extent -0.9,-1.55 0.9,1.55, height 1.45
SOT23_N [mm] "SOT23, 3-Leads, Body 2.9x1.3mm, Pitch 0.95mm, Lead Span 2.3mm, IPC Medium Density"
  rect 1.3x0.6 smd: 1(-1.05,0.95) 2(-1.05,-0.95) 3(1.05,0)
  silkscreen extent -1.17,-1.5 0.7,1.92, body extent -0.7,-1.5 0.7,1.5, height 1.1
SOT95P280X144-5M [mm] "SOT23, 5-Leads, Body 3,0x3,0mm (max), Pitch 0,95mm, IPC Low Density"
  rect 1.3x0.7 smd: 1(-1.2,0.95) 2(-1.2,0) 3(-1.2,-0.95) 4(1.2,-0.95) 5(1.2,0.95)
  silkscreen extent -1.32,-1.5 0.15,2.03, body extent -0.8,-1.5 0.8,1.5, height 1.44
SOT223_N [mm] "SOT223, 4-Leads, Body 6.5x3.5mm, Pitch 2.3mm, Lead Span 7mm, IPC Medium Density"
  rect 2.2x1 smd: 1(-3,2.3) 2(-3,0) 3(-3,-2.3)
  rect 2.2x3.3 smd: 4(3,0)
  silkscreen extent -3.12,-3.35 1.6,3.48, body extent -1.85,-3.35 1.85,3.35, height 1.8
"SOT353 for MC74HC" [mm] "SOT23, 5-Leads, Body 2,2x2,2mm (max), Pitch 0,65mm, IPC Low Density"
  rect 0.95x0.45 smd: 1(-1.025,0.65) 2(-1.025,0) 3(-1.025,-0.65) 4(1.025,-0.65) 5(1.025,0.65)
  silkscreen extent -1.15,-1.1 0.15,1.55, body extent -0.67,-1.1 0.67,1.1, height 1.1
TO228P1003X238-3N [mm] "D-PAK, 3-Pads, Body 6,3x6,7mm (max), IPC Medium Density"
  rect 2.25x1.3 smd: 1(-4.5,2.28) 3(-4.5,-2.28)
  rect 7.2x6.8 smd: 4(2,0)
  silkscreen extent -4.63,-3.35 -2,3.6, body extent -2.6,-3.35 3.75,3.35, height 2.38
TO254P1510-3_4N [mm] "D2-PAK, 4-Leads, Body 8.8x10.4mm, Pitch 2.54mm, Lead Span 15.1mm, IPC Medium Density"
  rect 2.4x1.05 smd: 1(-6.8,2.54) 3(-6.8,-2.54)
  rect 8.9x10.65 smd: 2(3.55,0)
  silkscreen extent -6.92,-5.25 -1.3,5.25, body extent -2.7,-5.28 6.3,5.28, height 4.69
uSOP8 [mm] "Shrink Small Outline; 8 Leads; Body Width 3 mm; Pitch 0.65 mm"
  rect 0.45x1.6 smd: 1(-0.975,-2.05) 2(-0.325,-2.05) 3(0.325,-2.05) 4(0.975,-2.05) 5(0.975,2.05) 6(0.325,2.05) 7(-0.325,2.05) 8(-0.975,2.05)
  silkscreen extent -1.87,-2.17 1.58,0.85, body extent -1.52,-1.52 1.52,1.52, height 1.5

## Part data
C1p C2 C5p C6p C7p C19 C52 C65: "Capacitor, standard"
C2p C3p C4p C39 C41 C42: "Capacitor for PRU etc."
C3 C4 C5 C6 C7 C8 C9 C9h C10 C11 C12 C12h C13 C14 C15 C16 C17 C18 C20 C21 C22 C23 C24 C25 C26 C27 C28 C29 C30 C31 C32 C33 C34 C35 C36 C37 C38 C40 C42h C43 C44 C45 C45h C46 C46h C47 C48 C49 C50 C51 C53 C54 C55 C56 C57 C58 C59 C62 C64 C66 C67 C68 C69: "Capacitor (Semiconductor SIM Model)"
C61: "Capacitor"
D1 D2 D3 D4: "Typical RED GaAs LED"
D1p: "High-Current Surface Mount Schottky Rectifier 3A"
J1: "USB 1.1, Right Angle, Thru-Hole, B Type, Receptacle, 4 Position, White"
J_AUX_RX J_LC J_TX_RX: "RF Coaxial PCB Connector, MCX; Thru-Hole, Right-Angle Mount Socket, Blunt Post Terminal, 50 Ohm Impedance"
LEDs: "Header, 12-Pin"
MF: library part CapacitorBig
P1: "Header, 2-Pin"
P2: "Header, 5-Pin, Dual row, Right Angle"
P3: "Header, 8-Pin, Dual row, Right Angle"
Q1: "P-channel Enhancement Mode Vertical D-MOSFET"
Q2 Q3 Q4: "N-channel Enhancement Mode MOSFET"
R1 R2 R2p R3 R4 R4p R5 R6 R7 R8 R9 R10 R11 R12 R13 R14 R15 R16 R17 R18 R19 R20 R21 R22 R23 R24 R25 R26 R27 R28 R29 R30 R31 R32 R33 R34: "Semiconductor Resistor"
S2: "RF Shielding"
U1: "8-Bit AVR Microcontroller with 32K Bytes of In-System Programmable Flash Memory"
U2: library part NJG1519KC1-TE3, "SP4T SWITCH GaAs MMIC, up to 2.5GHz."
U4: "2 way power splitter"
U5: "LNA from RFMD no external components"
U6 U8: "Voltage regulater from Microchip"
UA: library part TPS54332, "3.5A, 28V, 1MHz, STEP DOWN SWIFT DC/DC CONVERTER WITH Eco-mode™"
Utemp: "Digital Thermometer and Thermostat"
Uuhf: "ADF7021 transceiver"
VR1: "Voltage Regulator"
Y3: "FOX924B TCXO 19.44 MHz"

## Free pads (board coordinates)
  round 3.5 hole 2.6: 0(6.2,89.1)

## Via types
v1: diameter 0.7, hole 0.3, Top Layer to Bottom Layer, 290 vias
v2: diameter 0.7, hole 0.3, Top Layer to Bottom Layer, tented top, 19 vias
v3: diameter 0.6, hole 0.3, Top Layer to Bottom Layer, tented top, 16 vias
v4: diameter 6, hole 3.1, Top Layer to Bottom Layer, 4 vias
v5: diameter 0.66, hole 0.33, Top Layer to Bottom Layer, tented top, 4 vias
v6: diameter 4.5, hole 2.6, Top Layer to Bottom Layer, 2 vias

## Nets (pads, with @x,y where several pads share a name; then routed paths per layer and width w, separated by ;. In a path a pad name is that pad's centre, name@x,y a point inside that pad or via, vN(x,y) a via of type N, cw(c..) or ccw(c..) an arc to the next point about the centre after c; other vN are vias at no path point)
12V: P3.2 Q1.3 R25.2 | length 9.8
  Top Layer w0.3: Q1.3@17.3,62.5 17.35,62.55 17.35,64.75 17.929,65.329 R25.2@18.63,65.329
  Top Layer w0.8: P3.2@12.12,60.5 12.85,60.5 14.85,62.5 Q1.3@17.3,62.5
CE: U1.27 Uuhf.24 | length 43.4
  Top Layer w0.2: v2(55.6,38.1) 57.2,39.7 U1.27@57.2,43.85 ; Uuhf.24@69.75,15.425 69.75,14.5 70,14.25 v1(73.5,14.25)
  Bottom Layer w0.2: v2(55.6,38.1) 55.6,37.4 67,26 67,25.3 70.7,21.6 70.7,15.4 71.85,14.25 v1(73.5,14.25)
CLK_OUT: U1.9 Uuhf.36 | length 43
  Top Layer w0.2: U1.9@55.6,55.15 55.6,54.1 v1(56.2,53.5) ; Uuhf.36@70.575,21.75 71.15,21.75 72.1,22.7 v1(73.4,22.7)
  Bottom Layer w0.2: v1(56.2,53.5) 58.3,51.4 58.3,40.5 61.4,37.4 61.4,37.1 71.6,26.9 71.6,24.5 v1(73.4,22.7)
CPOUT: C55.2 R9.2 R10.2 Uuhf.42 | length 12.9
  Top Layer w0.2: C55.2@62.925,32.5 63,32.5 64,31.5 65.925,31.5 R9.2@66.925,30.5 R10.2@66.925,28.5 66.925,26.575 67.25,26.25 Uuhf.42@67.25,22.575
CREG3: C15.2 Uuhf.41 | length 10.3
  Top Layer w0.2: C15.2@66.925,32.5 67.75,31.675 Uuhf.41@67.75,22.575
D+: J1.3 R2.1 | length 12.6
  Top Layer w0.5: J1.3@11.41,76.25 10.15,76.25 9.6,75.7 9.6,73 11.2,71.4 16.692,71.4 R2.1@16.796,71.296
D-: J1.2 R1.1 | length 3.3
  Top Layer w0.5: J1.2@13.41,76.25 16.4,76.25 R1.1@16.65,76.5
DATA_CLK: U1.11 Uuhf.35 | length 43.3
  Top Layer w0.2: U1.11@54,55.15 54,54.4 v1(54.9,53.5) ; Uuhf.35@70.575,21.25 71.555,21.25 72.105,21.8 v1(72.2,21.8)
  Bottom Layer w0.2: v1(54.9,53.5) 54.9,53 57.2,50.7 57.2,38.5 67.6,28.1 68.5,28.1 70.4,26.2 70.4,23.5 72.1,21.8 v1(72.2,21.8)
DATA_IO: U1.10 Uuhf.34 | length 47.3
  Top Layer w0.2: U1.10@54.8,55.15 v2(54.8,56.6) ; Uuhf.34@70.575,20.75 71.55,20.75 71.9,21.1 72.9,21.1 v1(73.4,21.6)
  Bottom Layer w0.2: v2(54.8,56.6) 55.6,55.8 55.6,53 57.7,50.9 57.7,40.1 60.6,37.2 60.6,36.7 71,26.3 71,24 v1(73.4,21.6)
ENA: R2p.1 R4p.2 UA.3 | length 10.6
  Top Layer w0.5: R4p.2@28.751,81.17 R2p.1@28.751,83.156 28.816,83.09 UA.3@37.311,83.09
EXT_BEKO_PTT: P3.7 P3.8 Q3.3 | length 17.4
  Top Layer w0.3: P3.7@9.48,52.883 P3.8@12.02,52.883 20.017,52.883 21.626,51.274 Q3.3@26.191,51.274
EXT_BEKO_PTT_C: R28.2 U1.12 | length 22.2
  Top Layer w0.2: R28.2@30.35,53 30.85,53.5 U1.12@52.35,53.5
EXT_LNA_CONTROL: P3.3 P3.4 Q1.2 Q1.4 | length 16.6
  Top Layer w0.8: P3.3@9.48,57.963 P3.4@12.02,57.963 ; P3.4@12.12,57.96 15.64,57.96 17.1,56.5 Q1.4@19.6,56.5 Q1.2@19.6,62.5
EXT_LNA_CONTROL_C: R27.2 U1.22 | length 43.2
  Top Layer w0.2: v1(24.2,47.1) 26.4,47.1 28.6,44.9 36.9,44.9 38.3,46.3 50,46.3 50.9,45.4 52.25,45.4 U1.22@52.35,45.5 ; v1@30.35,56.5 R27.2@30.35,57.5
  Bottom Layer w0.2: v1(24.2,47.1) 24.2,50.4 30.15,56.35 v1@30.55,56.35
  other v1: 30.4,56.5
